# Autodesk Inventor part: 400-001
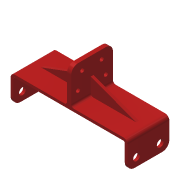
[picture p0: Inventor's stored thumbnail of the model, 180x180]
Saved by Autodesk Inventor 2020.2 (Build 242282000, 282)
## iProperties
Created: 2014-01
Part Number: 400-001
Material: Ogólny
Document SubType Name: Modeling
Designer: F.Stasiak
Density: 1 g/cm^3
Appearance: Jasnoczerwona
Manager: www.cadconsulting.pl
Company: Fabian Stasiak CAD Consulting
Author: F.Stasiak
Subject: Zbiór ćwiczeń. Autodesk Inventor 2020. Kurs podstawowy
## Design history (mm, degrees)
sketch "Szkic4"
  geometry: L1 (-400, 0)-(-400, -180); L2 (-400, -180)-(-420, -180); L3 (-420, -180)-(-420, 20); L4 (-400, 0)-(400, 0); L5 (400, 0)-(400, -180); L6 (400, -180)-(420, -180); L7 (420, -180)-(420, 20); L8 (420, 20)-(-420, 20); L9 (-15, 20)-(15, 20); L10 (15, 20)-(15, 270); L11 (15, 270)-(-15, 270); L12 (-15, 270)-(-15, 20); 3 further points
  constraints: 24 end point, 6 parallel, 3 horizontal, 3 midpoint, 3 perpendicular, 2 collinear, 1 coincident
  dimensions: "d12" = 20 distance of L1.end L2.end; "d15" = 800 distance between parallel lines of L5 L1; "d16" = 30 distance of L11.end L10.end; "d17" = 250 distance of L10.end L9.end; "d39" = 200 distance between parallel lines of L8 L2; "d40" = 20 distance between parallel lines of L8 L4
extrude "Wyciągnięcie proste3" new body sketch "Szkic4" stored distance "d18" = 300; taper "d19" = 0 deg
fillet "Zaokrąglenie1" dims "d20" = 10
fillet "Zaokrąglenie2" dims "d21" = 30
fillet "Zaokrąglenie3" dims "d22" = 20
sketch "Szkic5"
  geometry: L1 (11.606, 142.354)-(366.552, 10.821); 1 further point
  constraints: 2 end point
feature "Żebro1" sketch "Szkic5" dims "d23" = 1, "d24" = 20, "d25" = 0, "d26" = 0, "d27" = 1, "d28" = 1
mirror "Odbicie lustrzane1"
sketch "Szkic6"
  geometry: L1 (0, 170)-(300, 170) reference; L2 (0, 0)-(300, 0) reference; L3 (300, 170)-(300, 0) reference; L4 (65, 60)-(235, 60); 3 further points
  constraints: 2 end point, 2 midpoint, 1 perpendicular, 1 vertical alignment
  dimensions: "d30" = 170 distance of L4.start L4.end; "d31" = 60 distance between parallel lines of L4 L2
hole "Otwór1" sketch "Szkic6" at (65, 60), (235, 60) diameter "d32" = 50; stored, may be unused: countersink angle "d36" = 90 deg, drill point angle "d38" = 118 deg; dims "d33" = 6, "d34" = 4, "d35" = 2, "d37" = 8
hole "Otwór2" diameter "d43" = 30; stored, may be unused: countersink angle "d47" = 90 deg, drill point angle "d49" = 118 deg; dims "d41" = 50, "d42" = 60, "d44" = 6, "d45" = 4, "d46" = 2, "d48" = 8
hole "Otwór3" diameter "d52" = 30; stored, may be unused: countersink angle "d56" = 90 deg, drill point angle "d58" = 118 deg; dims "d50" = 60, "d51" = 80, "d53" = 6, "d54" = 4, "d55" = 2, "d57" = 8
mirror "Odbicie lustrzane2"
fillet "Zaokrąglenie4" dims "d59" = 50
fillet "Zaokrąglenie5" dims "d60" = 50
node "Bryła2"
